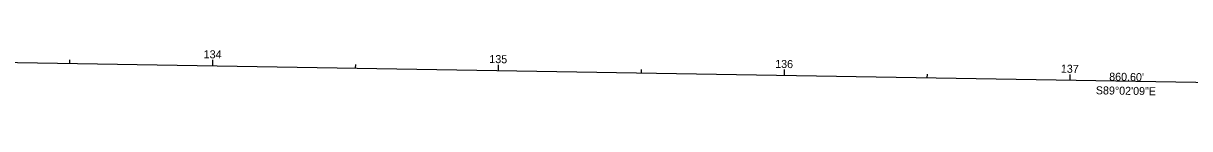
# Model space of a CAD drawing. Extents: x 2003596 to 2006888, y 572582 to 572983.
# Drawn here: x 2006067.5 to 2006475.6, y 572582.8 to 572600.8 of the extents above; entities that cross this region are included whole.
import ezdxf

# ---------------------------------------------------------------- set-up
doc = ezdxf.new("R2010")
doc.units = 0
for name, color, linetype in [('DR_X_Ditch', 7, 'Continuous'), ('PM_X_CL_Double_Solid', 7, 'Continuous'), ('PM_X_Edge_Line', 7, 'Continuous'), ('PM_X_Surveyed_Line', 7, 'Continuous'), ('PV_X_EOP', 7, 'Continuous'), ('RD_X_Fence', 7, 'Continuous'), ('SV_X_Break_Lines', 7, 'Continuous'), ('UT_X_Water', 7, 'Continuous'), ('UT_X_Water_Cells', 7, 'Continuous'), ('XS_X_Ground_Line', 7, 'Continuous')]:
    doc.layers.add(name, color=color, linetype=linetype)

msp = doc.modelspace()

# ---------------------------------------------------------------- linework, layer by layer
at = {"layer": 'DR_X_Ditch'}
for p, q in [((2006083.81, 572596.24), (2006083.83, 572597.44)), ((2006133.81, 572595.4), (2006133.84, 572597.4)), ((2006183.8, 572594.55), (2006183.82, 572595.75)), ((2006233.79, 572593.71), (2006233.82, 572595.71)), ((2006283.78, 572592.87), (2006283.8, 572594.07)), ((2006333.78, 572592.03), (2006333.81, 572594.03)), ((2006383.77, 572591.19), (2006383.79, 572592.39)), ((2006433.76, 572590.35), (2006433.8, 572592.35))]:
    msp.add_line(p, q, dxfattribs=at)
at = {"layer": 'PM_X_Surveyed_Line'}
msp.add_line((2006023.62, 572597.25), (2006884.1, 572582.77), dxfattribs=at)
at = {"layer": 'RD_X_Fence'}
for p, q in [((2006133.81, 572595.4), (2006133.83, 572596.6)), ((2006233.79, 572593.71), (2006233.82, 572595.71)), ((2006333.78, 572592.03), (2006333.8, 572593.23)), ((2006433.76, 572590.35), (2006433.78, 572591.55))]:
    msp.add_line(p, q, dxfattribs=at)
at = {"layer": 'UT_X_Water_Cells'}
msp.add_line((2006233.79, 572593.71), (2006233.81, 572594.91), dxfattribs=at)

# ---------------------------------------------------------------- texts
at = {"layer": 'DR_X_Ditch'}
for s, p in [('134', (2006130.61, 572598)), ('135', (2006230.54, 572596.32)), ('136', (2006330.54, 572594.63)), ('137', (2006430.47, 572592.95))]:
    msp.add_text(s, height=2.8, rotation=359.0359, dxfattribs=at).set_placement(p)
at = {"layer": 'PM_X_CL_Double_Solid'}
msp.add_text("860.60'", height=2.8, rotation=359.0359, dxfattribs=at).set_placement((2006447.38, 572590.17))
at = {"layer": 'PM_X_Edge_Line'}
msp.add_text("860.60'", height=2.8, rotation=359.0359, dxfattribs=at).set_placement((2006447.38, 572590.17))
at = {"layer": 'PV_X_EOP'}
msp.add_text('S89°02\'09"E', height=2.8, rotation=359.0359, dxfattribs=at).set_placement((2006442.71, 572585.4))
at = {"layer": 'RD_X_Fence'}
msp.add_text('135', height=2.8, rotation=359.0359, dxfattribs=at).set_placement((2006230.54, 572596.32))
at = {"layer": 'SV_X_Break_Lines'}
msp.add_text('S89°02\'09"E', height=2.8, rotation=359.0359, dxfattribs=at).set_placement((2006442.71, 572585.4))
at = {"layer": 'UT_X_Water'}
msp.add_text('S89°02\'09"E', height=2.8, rotation=359.0359, dxfattribs=at).set_placement((2006442.71, 572585.4))
at = {"layer": 'XS_X_Ground_Line'}
msp.add_text("860.60'", height=2.8, rotation=359.0359, dxfattribs=at).set_placement((2006447.38, 572590.17))

doc.saveas('drawing.dxf')
